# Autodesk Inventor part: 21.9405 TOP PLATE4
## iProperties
Created: 2010-10
Part Number: 21.9405 TOP PLATE4
Document SubType Name: Modeling
Designer: Administrator
Density: 1 g/cm^3
Mass: 103.855 g
Surface Area: 396.205 cm^2
Volume: 103.855 cm^3
Author: Administrator
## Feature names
1. Base1
